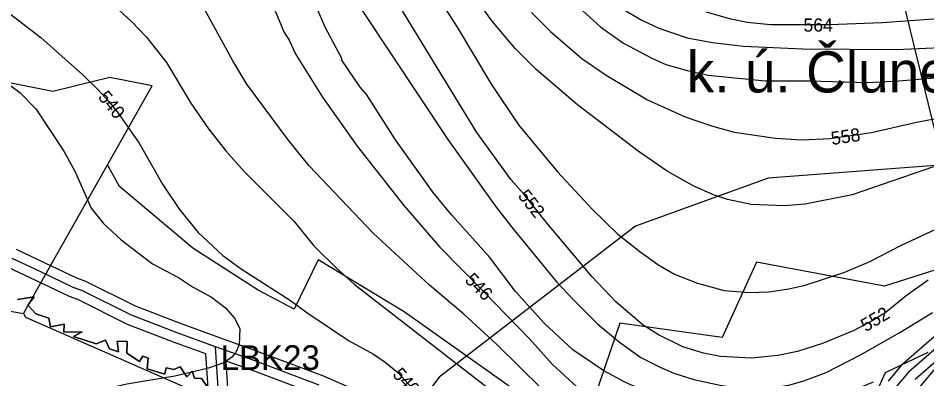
# Model space of a CAD drawing. Extents: x -709418 to -703832, y -1161719 to -1157826.
# Drawn here: x -707566 to -707015, y -1158707 to -1158488 of the extents above; entities that cross this region are included whole.
import ezdxf

# ---------------------------------------------------------------- set-up
doc = ezdxf.new("R2010")
doc.units = 0
for name, color, linetype in [('102_obvod PÚ', 7, 'Continuous'), ('103_hranice KÚ', 7, 'Continuous'), ('104_název KÚ', 7, 'Continuous'), ('120_vrstevnice hlavní', 7, 'Continuous'), ('121_vrstevnice hlavní_popis', 7, 'Continuous'), ('122_vrstevnice základní', 7, 'Continuous'), ('206_TTP_KN', 7, 'Continuous'), ('501_vodní tok', 7, 'Continuous'), ('514 odvodnění - LPIS', 7, 'Continuous'), ('606_RBC_návrh', 7, 'Continuous'), ('609_LBC_stav', 7, 'Continuous'), ('611_LBK_stav', 7, 'Continuous'), ('612_LBK_stav_popis', 7, 'Continuous'), ('723_radioreléová trasa_UAP', 7, 'Continuous'), ('735_OP sítí TI', 7, 'Continuous')]:
    doc.layers.add(name, color=color, linetype=linetype)

msp = doc.modelspace()

# ---------------------------------------------------------------- linework, layer by layer
at = {"layer": '102_obvod PÚ'}
msp.add_lwpolyline([(-707566.82, -1158658.76), (-707556.62, -1158657.09), (-707560.54, -1158662.15), (-707555.69, -1158667.38), (-707547.86, -1158670.03), (-707546.73, -1158675.37), (-707538.44, -1158673.71), (-707538.69, -1158678.51), (-707527.5, -1158678.32), (-707532.85, -1158681.16), (-707519.05, -1158685.71), (-707513.46, -1158683.35), (-707510.86, -1158688.8), (-707505.51, -1158690.57), (-707506.29, -1158684.14), (-707500.16, -1158684.19), (-707500.4, -1158691.4), (-707492.77, -1158696.31), (-707490.78, -1158693.12), (-707487.46, -1158694.48), (-707488.03, -1158700.81), (-707477.33, -1158704.18), (-707476.45, -1158700.35), (-707471.85, -1158701.33), (-707468.09, -1158699.73), (-707463.92, -1158705.77), (-707460.7, -1158702.19), (-707459.23, -1158706.6), (-707455.06, -1158706.65), (-707446.91, -1158718.31)], dxfattribs=at)
at = {"layer": '103_hranice KÚ'}
for points in [[(-707446.91, -1158718.31), (-707455.06, -1158706.65), (-707459.23, -1158706.6), (-707460.7, -1158702.19), (-707463.92, -1158705.77), (-707468.09, -1158699.73), (-707471.85, -1158701.33), (-707476.45, -1158700.35), (-707477.33, -1158704.18), (-707488.03, -1158700.81), (-707487.46, -1158694.48), (-707490.78, -1158693.12), (-707492.77, -1158696.31), (-707500.4, -1158691.4), (-707500.16, -1158684.19), (-707506.29, -1158684.14), (-707505.51, -1158690.57), (-707510.86, -1158688.8), (-707513.46, -1158683.35), (-707519.05, -1158685.71), (-707532.85, -1158681.16), (-707527.5, -1158678.32), (-707538.69, -1158678.51), (-707538.44, -1158673.71), (-707546.73, -1158675.37), (-707547.86, -1158670.03), (-707555.69, -1158667.38), (-707560.54, -1158662.15), (-707556.62, -1158657.09), (-707566.82, -1158658.76)], [(-707013.93, -1158690.96), (-707030.94, -1158699.07), (-707039.78, -1158703.27), (-707049.41, -1158724.29)]]:
    msp.add_lwpolyline(points, dxfattribs=at)
at = {"layer": '120_vrstevnice hlavní'}
for points in [[(-707228, -1158479.42), (-707212.57, -1158493.28), (-707198.72, -1158502.99), (-707181.57, -1158512.13), (-707173, -1158515.99), (-707160.14, -1158519.71), (-707147.28, -1158522.42), (-707112.71, -1158525.85), (-707085.85, -1158525.85), (-707050.42, -1158526.99), (-707031.56, -1158525.99), (-706997.56, -1158523.14)], [(-707577.16, -1158480.7), (-707552.59, -1158499.56), (-707526.87, -1158522.56), (-707518.02, -1158531.14), (-707511.3, -1158538.42), (-707505.73, -1158545.56), (-707493.01, -1158563.85), (-707478.73, -1158588.71), (-707468.44, -1158604.14), (-707457.01, -1158618.14), (-707442.01, -1158632), (-707431.01, -1158640.14), (-707401.01, -1158659.28), (-707391.15, -1158666.57), (-707365.72, -1158683.71), (-707350.58, -1158692), (-707343.44, -1158696.86), (-707335.72, -1158703.14), (-707327.01, -1158712.72)], [(-707357.58, -1158483.28), (-707305.43, -1158561.56), (-707276.15, -1158602.71), (-707265.15, -1158616.71), (-707239.15, -1158648.14), (-707229.29, -1158658.71), (-707214.29, -1158673.71), (-707201.29, -1158684.57), (-707188.14, -1158694), (-707176.14, -1158700.14), (-707168.14, -1158703.57), (-707156.14, -1158707.43), (-707140.14, -1158710.86), (-707132.14, -1158712), (-707116.14, -1158712.72), (-707107.57, -1158712.29), (-707098.42, -1158710.86), (-707089.28, -1158708.14), (-707075.57, -1158703.14), (-707054.85, -1158692.29), (-707030.99, -1158678.86), (-707010.99, -1158666.71)]]:
    msp.add_lwpolyline(points, dxfattribs=at)
at = {"layer": '122_vrstevnice základní'}
for points in [[(-707579.31, -1158433.13), (-707561.3, -1158441.42), (-707550.45, -1158447.27), (-707543.3, -1158451.84), (-707519.3, -1158469.85), (-707497.44, -1158489.99), (-707488.44, -1158499.42), (-707476.3, -1158514.85), (-707461.44, -1158539.56), (-707450.73, -1158554.99), (-707440.3, -1158568.42), (-707429.15, -1158580.99), (-707398.72, -1158611.42), (-707386.79, -1158626.05), (-707373.3, -1158639.57), (-707362.29, -1158649.43)], [(-707047.11, -1158708.95), (-707082.14, -1158723.43), (-707100.43, -1158726.72), (-707119, -1158728.29), (-707143, -1158726.14), (-707161.62, -1158722.43), (-707174.43, -1158718.43), (-707188.86, -1158713), (-707197.86, -1158709), (-707210.72, -1158702.14), (-707229.57, -1158689.29), (-707247, -1158673.14), (-707264.43, -1158653.85), (-707280, -1158633.28), (-707303.01, -1158607.57), (-707314.43, -1158593.85), (-707337.29, -1158561.85), (-707354.72, -1158534.42), (-707358.72, -1158529.85), (-707369.87, -1158513.28), (-707369.87, -1158512.42), (-707379.87, -1158493.28), (-707390.72, -1158468.13)], [(-707415.58, -1158470.42), (-707405.01, -1158496.13), (-707401.87, -1158501.28), (-707397.72, -1158509.85), (-707381.58, -1158535.85), (-707360.44, -1158565.56), (-707332.15, -1158601.57), (-707310.29, -1158627), (-707283.72, -1158653.85), (-707255.86, -1158682.71), (-707241.86, -1158698.14), (-707227.15, -1158711.86), (-707215.57, -1158719.72), (-707188.43, -1158733.29), (-707172.14, -1158739.29), (-707160.71, -1158741.72), (-707134.71, -1158745.43), (-707101, -1158746.29), (-707088.99, -1158744.57), (-707076.55, -1158741.26), (-707067.71, -1158737)], [(-707312.86, -1158472.7), (-707299.72, -1158493.28), (-707279.43, -1158527.56), (-707262.58, -1158552.71), (-707238.86, -1158581.28), (-707217.86, -1158603.85), (-707202.14, -1158619), (-707188.86, -1158629.57), (-707177.86, -1158637.43), (-707167.86, -1158643.43), (-707153.86, -1158648.85), (-707137.57, -1158653.28), (-707122.3, -1158654.55), (-707110.43, -1158654.14), (-707098.42, -1158652.28), (-707088.42, -1158650), (-707064.42, -1158642.14), (-707049.14, -1158635.57), (-707029.85, -1158625.71), (-706997.28, -1158610.57)], [(-707219.14, -1158470.42), (-707187.57, -1158488.99), (-707177.29, -1158493.85), (-707160.14, -1158499.71), (-707144.71, -1158502.56), (-707125.85, -1158504.85), (-707089.85, -1158506.56), (-707032.99, -1158506.85), (-706943.99, -1158502.85)], [(-707097.68, -1158793.36), (-707099.57, -1158782.72), (-707101.91, -1158779.2), (-707107.29, -1158773.61), (-707117.28, -1158768.29), (-707120.71, -1158767), (-707136.14, -1158763.57), (-707172.14, -1158758.15), (-707196.43, -1158751), (-707214.43, -1158743), (-707225.72, -1158734.43), (-707234.57, -1158726.57), (-707275.72, -1158686.14), (-707295.72, -1158667.71), (-707316.58, -1158650), (-707350.72, -1158618.43), (-707389.72, -1158577.57), (-707402.44, -1158561.71), (-707427.58, -1158527.99), (-707436.01, -1158513.85), (-707456.58, -1158475.85)], [(-707013.71, -1158647), (-707026.99, -1158656.57), (-707039.28, -1158666.43), (-707047.42, -1158671.57), (-707059.28, -1158677.71), (-707077.85, -1158685.57), (-707093, -1158690.29), (-707105, -1158692.86), (-707121, -1158694.43), (-707139.85, -1158693.29), (-707150.14, -1158691.29), (-707162.71, -1158687.57), (-707177.57, -1158680.29), (-707186.86, -1158674.29), (-707203.14, -1158660.43), (-707218, -1158644.71), (-707245.72, -1158611.71), (-707259.01, -1158595.05), (-707267, -1158586), (-707287.86, -1158557.28), (-707334.01, -1158481.85)], [(-707010.42, -1158578.14), (-707059.85, -1158595.14), (-707088.42, -1158600.85), (-707101.28, -1158601.85), (-707121.28, -1158601.14), (-707135.57, -1158598), (-707144.14, -1158595.14), (-707156.14, -1158590), (-707172.14, -1158580.85), (-707189.86, -1158568.71), (-707226.72, -1158540.42), (-707251.86, -1158519.13), (-707264.58, -1158506.28), (-707278.43, -1158489.71), (-707285.29, -1158480.56)], [(-707254.72, -1158484.42), (-707243, -1158495.99), (-707224.14, -1158512.42)], [(-706971.56, -1158487.85), (-707007.56, -1158488.28), (-707041.57, -1158490.7), (-707073.57, -1158491.99), (-707109.57, -1158491.99), (-707123.57, -1158490.42), (-707133.57, -1158488.56), (-707148.43, -1158484.13)], [(-707633.59, -1158491.99), (-707597.02, -1158511.71), (-707579.02, -1158522.99), (-707565.16, -1158533.28), (-707555.73, -1158542.85), (-707538.59, -1158568.71), (-707531.87, -1158581.28), (-707522.02, -1158603.28), (-707514.59, -1158612.57), (-707503.87, -1158622.57), (-707484.87, -1158637), (-707469.01, -1158645.43), (-707460.44, -1158651), (-707449.01, -1158657.28), (-707440.58, -1158663.71), (-707435.01, -1158670), (-707431.87, -1158676.29)], [(-707224.14, -1158512.42), (-707209.29, -1158522.56), (-707184.14, -1158537.42), (-707161.29, -1158547.85), (-707145.28, -1158553.28), (-707131.57, -1158557.14), (-707106.43, -1158560.71), (-707090.42, -1158561.85), (-707073.28, -1158560.99), (-707048.14, -1158557.28), (-707020.71, -1158550.99), (-706994.99, -1158546.14)], [(-707050.78, -1158757.61), (-707024.44, -1158718.68), (-707009.56, -1158700.86), (-706991.71, -1158685), (-706981.85, -1158679.29), (-706956.56, -1158668.71), (-706936.99, -1158661.43), (-706929.27, -1158656.57), (-706926.7, -1158651), (-706926.7, -1158649.57), (-706929.56, -1158645.57), (-706935.27, -1158645.28), (-706953, -1158648.39)], [(-707362.29, -1158649.43), (-707282.18, -1158711.66), (-707280.58, -1158714.72), (-707277.29, -1158727.57), (-707276.72, -1158744.15), (-707277.43, -1158759.86), (-707275.29, -1158771), (-707271.86, -1158776.72), (-707265.58, -1158782.72), (-707257.29, -1158787.29), (-707252.15, -1158788.86), (-707244.43, -1158790), (-707233.86, -1158790), (-707213.86, -1158788.43), (-707200.14, -1158788.43), (-707176.71, -1158790.58), (-707171.29, -1158792.29), (-707164.57, -1158798.58)], [(-707431.87, -1158676.29), (-707432.25, -1158686.35), (-707434.43, -1158691.15), (-707436.61, -1158693.77), (-707441.41, -1158697.26), (-707450.73, -1158700.43), (-707471.21, -1158705.33), (-707500.44, -1158710.14), (-707509.02, -1158712.14), (-707517.59, -1158715), (-707526.16, -1158718.86), (-707543.3, -1158730.29), (-707566.16, -1158747.29), (-707571.88, -1158750.86)]]:
    msp.add_lwpolyline(points, dxfattribs=at)
at = {"layer": '206_TTP_KN'}
for p, q in [((-707566.82, -1158658.76), (-707556.62, -1158657.09)), ((-707556.62, -1158657.09), (-707560.54, -1158662.15)), ((-707560.54, -1158662.15), (-707555.69, -1158667.38)), ((-707555.69, -1158667.38), (-707547.86, -1158670.03)), ((-707547.86, -1158670.03), (-707546.73, -1158675.37)), ((-707546.73, -1158675.37), (-707538.44, -1158673.71)), ((-707538.44, -1158673.71), (-707538.69, -1158678.51)), ((-707538.69, -1158678.51), (-707527.5, -1158678.32)), ((-707527.5, -1158678.32), (-707532.85, -1158681.16)), ((-707532.85, -1158681.16), (-707519.05, -1158685.71)), ((-707519.05, -1158685.71), (-707513.46, -1158683.35)), ((-707513.46, -1158683.35), (-707510.86, -1158688.8)), ((-707505.51, -1158690.57), (-707506.29, -1158684.14)), ((-707506.29, -1158684.14), (-707500.16, -1158684.19)), ((-707510.86, -1158688.8), (-707505.51, -1158690.57)), ((-707500.16, -1158684.19), (-707500.4, -1158691.4)), ((-707500.4, -1158691.4), (-707492.77, -1158696.31)), ((-707492.77, -1158696.31), (-707490.78, -1158693.12)), ((-707490.78, -1158693.12), (-707487.46, -1158694.48)), ((-707487.46, -1158694.48), (-707488.03, -1158700.81)), ((-707477.33, -1158704.18), (-707476.45, -1158700.35)), ((-707476.45, -1158700.35), (-707471.85, -1158701.33)), ((-707471.85, -1158701.33), (-707468.09, -1158699.73)), ((-707468.09, -1158699.73), (-707463.92, -1158705.77)), ((-707488.03, -1158700.81), (-707477.33, -1158704.18)), ((-707463.92, -1158705.77), (-707460.7, -1158702.19)), ((-707460.7, -1158702.19), (-707459.23, -1158706.6)), ((-707459.23, -1158706.6), (-707455.06, -1158706.65)), ((-707455.06, -1158706.65), (-707446.91, -1158718.31))]:
    msp.add_line(p, q, dxfattribs=at)
at = {"layer": '501_vodní tok'}
for points in [[(-707383.58, -1158710.72), (-707423.65, -1158695.69), (-707446.61, -1158687.49), (-707469.93, -1158678.95), (-707497.63, -1158668.35), (-707527.74, -1158653.27), (-707533.02, -1158651.42), (-707552.66, -1158642.03), (-707570.15, -1158633.83)], [(-706999.37, -1158680.06), (-707025.87, -1158703.05), (-707033.45, -1158712.1)], [(-707431.27, -1159133.64), (-707440.11, -1159121.8), (-707449.81, -1159100.97), (-707464.65, -1159056.46), (-707472.65, -1159028.58), (-707473.27, -1159021.56), (-707466.93, -1158948.04), (-707455.38, -1158835.34), (-707453.67, -1158804.53), (-707445.22, -1158719.47), (-707444.82, -1158715.51), (-707446.61, -1158687.49)]]:
    msp.add_lwpolyline(points, dxfattribs=at)
at = {"layer": '514 odvodnění - LPIS'}
msp.add_lwpolyline([(-707008.65, -1157850.62), (-707020.37, -1157868.34), (-707032.18, -1157909.71), (-706983.9, -1157980.47), (-706961.3, -1157988.78), (-706842.86, -1157929.78), (-706777.34, -1157958.78), (-706811.96, -1158080.45), (-706902.81, -1158081.49), (-707093.53, -1158220.83), (-707105.15, -1158353.92), (-707074.8, -1158383.37), (-706961.71, -1158400.07), (-706842.82, -1158382.87), (-706781.21, -1158533.83), (-706846.65, -1158565.03), (-707110.93, -1158585.03), (-707191.51, -1158614.18), (-707310.74, -1158705.87), (-707472.83, -1158919.53), (-707502.65, -1158935.48), (-707489.16, -1159005.71), (-707569.43, -1159066.92)], dxfattribs=at)
at = {"layer": '606_RBC_návrh'}
msp.add_lwpolyline([(-707619.1, -1158657.4), (-707563.23, -1158667.28), (-707485.12, -1158528.92), (-707510.83, -1158523.97), (-707545.43, -1158532.37), (-707617.61, -1158518.04)], dxfattribs=at)
at = {"layer": '609_LBC_stav'}
msp.add_lwpolyline([(-706844.95, -1158588.47), (-707040.27, -1158650.67), (-707118.06, -1158635.99), (-707138.8, -1158681.77), (-707201.03, -1158673.13), (-707254.61, -1158830.36), (-707252.02, -1158852.82)], dxfattribs=at)
at = {"layer": '611_LBK_stav'}
for points in [[(-707224.69, -1158742.58), (-707242.34, -1158729.79), (-707332.02, -1158666.22), (-707384.2, -1158634.71), (-707398.88, -1158664.59), (-707420.62, -1158653.18), (-707460.3, -1158627.65), (-707504.87, -1158590.16), (-707512.19, -1158576.86)], [(-707563.23, -1158667.28), (-707561.95, -1158669.48), (-707419.53, -1158731.96), (-707418.99, -1158720.55), (-707364.64, -1158729.25), (-707345.07, -1158796.62), (-707332.02, -1158809.11), (-707311.37, -1158814), (-707252.02, -1158852.82)]]:
    msp.add_lwpolyline(points, dxfattribs=at)
at = {"layer": '723_radioreléová trasa_UAP'}
msp.add_lwpolyline([(-707182.2, -1157850.62), (-706271.36, -1161577.76)], dxfattribs=at)
at = {"layer": '735_OP sítí TI'}
for points in [[(-707360.14, -1158714.5), (-707381.32, -1158705.16), (-707421.59, -1158690.06), (-707444.57, -1158681.85), (-707467.83, -1158673.33), (-707495.21, -1158662.85), (-707525.4, -1158647.74), (-707530.73, -1158645.86), (-707550.09, -1158636.61), (-707567.47, -1158628.46)], [(-707452.35, -1158691.78), (-707472.04, -1158684.57), (-707500.05, -1158673.85), (-707530.09, -1158658.81), (-707535.32, -1158656.97), (-707555.22, -1158647.46), (-707572.83, -1158639.2)], [(-707002.27, -1158674.63), (-707030.16, -1158698.83), (-707038.07, -1158708.28)], [(-706996.48, -1158685.5), (-707021.58, -1158707.27)], [(-707479.03, -1159018.48), (-707479.03, -1159018.48), (-707479.03, -1159018.48), (-707472.91, -1158947.48), (-707461.36, -1158834.87), (-707459.65, -1158804.07), (-707451.19, -1158718.88), (-707450.84, -1158715.41), (-707452.35, -1158691.78)], [(-707410.36, -1159140.14), (-707427.1, -1159129.19), (-707434.94, -1159118.7), (-707444.23, -1159098.75), (-707458.92, -1159054.68), (-707466.72, -1159027.48), (-707467.25, -1159021.55), (-707460.96, -1158948.6), (-707449.4, -1158835.82), (-707447.68, -1158804.99), (-707439.24, -1158720.07), (-707438.8, -1158715.62), (-707440.04, -1158696.21)], [(-707385.85, -1158716.28), (-707425.72, -1158701.33), (-707440.04, -1158696.21)]]:
    msp.add_lwpolyline(points, dxfattribs=at)

# ---------------------------------------------------------------- texts
at = {"layer": '104_název KÚ'}
msp.add_text('k. ú. Člunek', height=25, dxfattribs=at).set_placement((-707160.35, -1158533))
at = {"layer": '121_vrstevnice hlavní_popis'}
for s, rotation, p in [('564', 0.3279, (-707089.44, -1158496.06)), ('540', 308.6859, (-707518.32, -1158535.93)), ('558', 8.2682, (-707072.16, -1158564.93)), ('552', 308.4437, (-707263.31, -1158595.92)), ('546', 314.8312, (-707295.65, -1158647.44)), ('552', 30.6017, (-707051.67, -1158678.68)), ('540', 311.95, (-707339.52, -1158704.59))]:
    msp.add_text(s, height=8, rotation=rotation, dxfattribs=at).set_placement(p)
at = {"layer": '612_LBK_stav_popis'}
msp.add_text('LBK23', height=15, dxfattribs=at).set_placement((-707443.4, -1158701.54))

doc.saveas('drawing.dxf')
